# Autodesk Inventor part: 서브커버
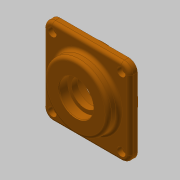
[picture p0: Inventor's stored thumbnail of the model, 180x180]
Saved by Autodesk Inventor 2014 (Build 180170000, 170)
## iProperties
Created: 2018-09
Part Number: 서브커버
Material: 알루미늄 6061
Document SubType Name: Modeling
Designer: mduedu
Density: 1 g/cm^3
Appearance: 주황색
Author: mduedu
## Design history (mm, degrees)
sketch "스케치1"
  geometry: L1 (-40, -40)-(40, -40); L2 (40, -40)-(40, 40); L3 (40, 40)-(-40, 40); L4 (-40, 40)-(-40, -40); L5 (-40, -40)-(40, 40); L6 (40, -40)-(-40, 40); 1 further point
  constraints: 12 end point, 2 midpoint, 2 parallel, 1 horizontal, 1 perpendicular
  dimensions: "d0" = 80 distance of L3.end L2.end; "d1" = 80 distance of L2.end L1.end
extrude "돌출1" new body sketch "스케치1" distance "d2" = 7; taper "d3" = 0 deg
sketch "스케치2"
  geometry: C1 r 30 at (0, 0); 1 further point
  constraints: 1 centre point, 1 coincident
  dimensions: "d4" = 60 diameter of C1
extrude "돌출2" join sketch "스케치2" distance "d5" = 10; taper "d6" = 0 deg
sketch "스케치3"
  geometry: C1 r 32.5 at (0, 0); 1 further point
  constraints: 1 centre point, 1 coincident
  dimensions: "d7" = 65 diameter of C1
extrude "돌출3" join sketch "스케치3" distance "d8" = 9; taper "d9" = 0 deg
sketch "스케치4"
  geometry: L1 (-32.5, -9)-(32.5, -9) reference; L2 (30, 17)-(-30, 17) reference; L3 (0, 17)-(0, -9); L4 (0, -9)-(20, -9); L5 (20, -9)-(20, 3); L6 (20, 3)-(0, 3); L7 (0, 3)-(0, -9); L8 (0, 3)-(12.5, 3); L9 (12.5, 3)-(12.5, 8.7); L10 (12.5, 8.7)-(0, 8.7); L11 (0, 8.7)-(0, 3); L12 (0, 8.7)-(16, 8.7); L13 (16, 8.7)-(16, 17); L14 (16, 17)-(0, 17); L15 (0, 17)-(0, 8.7); 1 further point
  constraints: 26 end point, 6 parallel, 3 horizontal, 3 perpendicular, 2 midpoint, 1 point on line
  dimensions: "d10" = 12 distance of L4.end L5.end; "d12" = 8.3 distance of L12.end L13.end; "d13" = 32 diameter of L13 L3; "d14" = 25 diameter of L9 L3; "d15" = 40 diameter of L5 L3
revolve "회전1" sketch "스케치4" stored, may be unused: angle "d16" = 90 deg
fillet "모깎기1" dims "d17" = 8
fillet "모깎기2" dims "d18" = 3
fillet "모깎기3" dims "d19" = 3
chamfer "모따기1" distance "d20" = 0.8; stored, may be unused: second distance "d21" = 2, angle "d22" = 30 deg
chamfer "모따기2" distance "d23" = 1; stored, may be unused: second distance "d24" = 2, angle "d25" = 30 deg
fillet "모깎기4" dims "d26" = 0.3
sketch "스케치5"
  geometry: A1 r 8 centre (-32, 32) between (-32, 40) and (-40, 32) reference; A2 r 8 centre (-32, -32) between (-40, -32) and (-32, -40) reference; A3 r 8 centre (32, -32) between (32, -40) and (40, -32) reference; A4 r 8 centre (32, 32) between (40, 32) and (32, 40) reference; 5 further points
  constraints: 4 coincident
hole "구멍1" sketch "스케치5" at (-32, 32), (32, 32), (32, -32), (-32, -32) diameter "d27" = 4.5; stored, may be unused: countersink angle "d31" = 90 deg, drill point angle "d33" = 118 deg; dims "d28" = 6, "d29" = 8, "d30" = 4.4, "d32" = 8
node "솔리드1"
